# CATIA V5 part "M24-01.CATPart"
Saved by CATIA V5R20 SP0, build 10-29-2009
Part number: M24-01
Revision: ANY
Definition: UNKNOWN
Nomenclature: M24-01
Source: Unknown
Bounding box of the stored display mesh (mm): x -12 to 12, y -11.818 to 11.818, z 0 to 290
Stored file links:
  C:\Users\Utente\Desktop\IO LAVORO\3D X SITO CF\X 3D SITO CF 27-09-2020\740T\740T-24\M24-01.CATPart
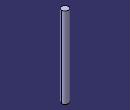
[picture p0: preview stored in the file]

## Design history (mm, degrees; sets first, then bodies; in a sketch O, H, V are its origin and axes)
Body1 "NONE" (main body)
  Solid1: solid without history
